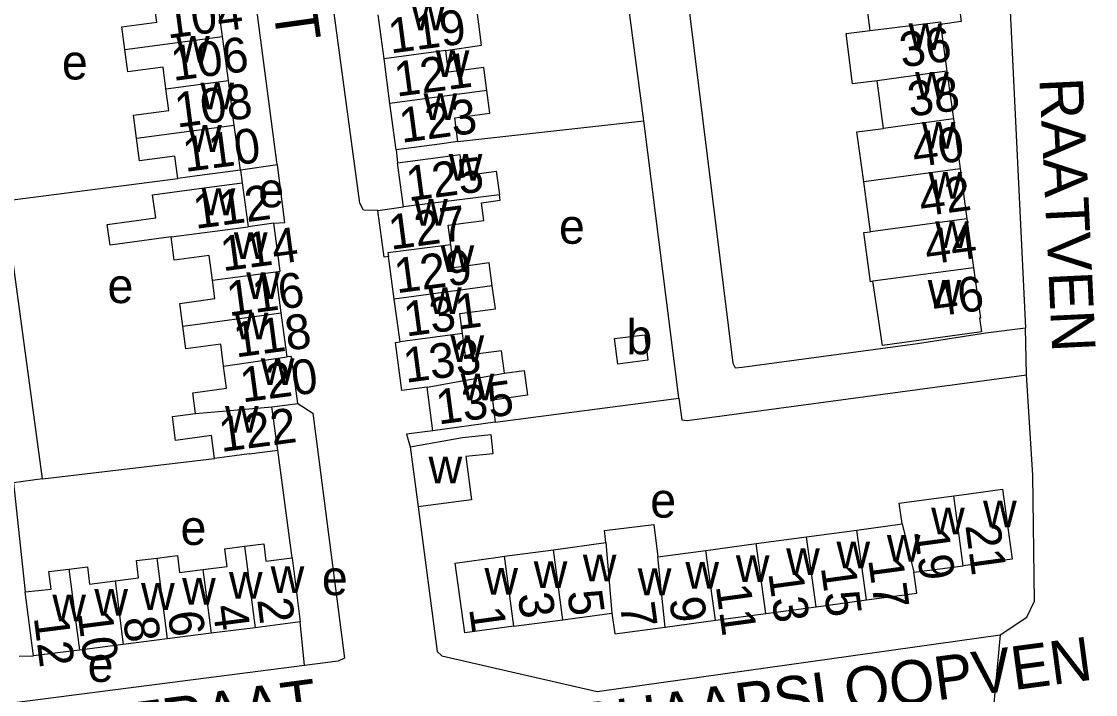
# Model space of a CAD drawing. Extents: x 162667 to 164645, y 379003 to 382150.
# Drawn here: x 163473.8 to 163597.3, y 381098.1 to 381175.5 of the extents above; entities that cross this region are included whole.
import ezdxf

# ---------------------------------------------------------------- set-up
doc = ezdxf.new("R2010")
doc.units = 0
for name, color, linetype in [('BLT_Basislijn', 7, 'Continuous'), ('BLT_Bebouwing', 7, 'Continuous'), ('BLT_Centroide', 7, 'Continuous'), ('BLT_Huisnummer', 7, 'Continuous'), ('BLT_Huisnummer_ tussenligend', 7, 'Continuous'), ('BLT_Onderverdeling_panden', 7, 'Continuous'), ('BLT_Straatnaam', 7, 'Continuous'), ('BLT_Vlakafsluiter', 7, 'Continuous')]:
    doc.layers.add(name, color=color, linetype=linetype)

msp = doc.modelspace()

# ---------------------------------------------------------------- linework, layer by layer
at = {"layer": 'BLT_Basislijn'}
for p, q in [((163545.35, 381164.05), (163541.22, 381195.04)), ((163586.86, 381189.28), (163589.19, 381140.23)), ((163523.97, 381161.65), (163545.35, 381164.05)), ((163516.88, 381160.7), (163517.04, 381159.2)), ((163503.22, 381158.97), (163498.97, 381158.38)), ((163498.97, 381158.38), (163499.18, 381156.92)), ((163471.9, 381154.85), (163491.77, 381157.41)), ((163476.23, 381122.88), (163471.97, 381154.32)), ((163589.34, 381134.85), (163589.19, 381140.23)), ((163528.27, 381129.39), (163549.38, 381132.18)), ((163504.92, 381113.81), (163503.26, 381126.2)), ((163476.23, 381122.88), (163496, 381125.22)), ((163506.35, 381101.46), (163505.85, 381106.45)), ((163473.56, 381102.51), (163475.18, 381102.55))]:
    msp.add_line(p, q, dxfattribs=at)
for points in [[(163546.24, 381211.73), (163555.57, 381136.18), (163555.85, 381135.67), (163556.64, 381135.74), (163576.78, 381138.45), (163584.66, 381139.68), (163589.19, 381140.23)], [(163514.78, 381153.75), (163513.12, 381153.77), (163512.72, 381154.57), (163507.84, 381190.6)], [(163503.22, 381158.97), (163503.18, 381159.27), (163499.22, 381189.4)], [(163549.38, 381132.18), (163549.33, 381132.5), (163545.35, 381164.05)], [(163502.83, 381152.26), (163504.07, 381152.35), (163503.22, 381158.97)], [(163549.38, 381132.18), (163549.72, 381129.68), (163550.31, 381129.61), (163589.34, 381134.85)], [(163586.31, 381104.98), (163589.37, 381107), (163590.24, 381108.83), (163590.03, 381123.33), (163589.34, 381134.85)], [(163505.58, 381131.57), (163507.29, 381130.46), (163510.93, 381102.28), (163510.22, 381101.93), (163506.35, 381101.46)], [(163521.1, 381128.43), (163518.08, 381128.03), (163518.48, 381126.56)], [(163476.23, 381122.88), (163472.91, 381122.44), (163474.24, 381109.92)], [(163519.41, 381119.67), (163521.6, 381103.05), (163522.14, 381102.57), (163539.99, 381098.46), (163586.31, 381104.98)], [(163506.35, 381101.46), (163450.08, 381094.2), (163448.63, 381104.37)]]:
    msp.add_lwpolyline(points, dxfattribs=at)
at = {"layer": 'BLT_Bebouwing'}
for p, q in [((163496.9, 381173.74), (163496.23, 381178.79)), ((163515.48, 381171.16), (163514.8, 381176.2)), ((163579.45, 381175.11), (163580.18, 381169.73)), ((163497.59, 381168.67), (163496.9, 381173.74)), ((163516.16, 381166.04), (163515.48, 381171.16)), ((163580.18, 381169.73), (163580.92, 381164.26)), ((163498.27, 381163.55), (163497.59, 381168.67)), ((163572.88, 381163.17), (163572.14, 381168.63)), ((163516.88, 381160.7), (163516.16, 381166.04)), ((163498.97, 381158.38), (163498.27, 381163.55)), ((163580.92, 381164.26), (163581.7, 381158.51)), ((163517.72, 381154.14), (163517.04, 381159.2)), ((163581.7, 381158.51), (163582.47, 381152.77)), ((163571.39, 381151.29), (163570.62, 381157.02)), ((163499.18, 381156.92), (163499.86, 381151.85)), ((163514.78, 381153.75), (163517.72, 381154.14)), ((163502.83, 381152.26), (163499.86, 381151.85)), ((163582.47, 381152.77), (163583.23, 381147.15)), ((163516.66, 381143.55), (163516.01, 381148.43)), ((163503.67, 381141.96), (163503.03, 381146.69)), ((163517.32, 381138.64), (163516.66, 381143.55)), ((163504.34, 381136.9), (163503.67, 381141.96)), ((163521.1, 381128.43), (163520.43, 381133.44)), ((163502.59, 381131.17), (163505.58, 381131.57)), ((163503.26, 381126.2), (163502.59, 381131.17)), ((163528.27, 381129.39), (163521.1, 381128.43)), ((163500, 381125.76), (163503.26, 381126.2)), ((163518.48, 381126.56), (163519.41, 381119.67)), ((163569.84, 381117.01), (163575.02, 381117.71)), ((163558.27, 381115.45), (163564.05, 381116.23)), ((163564.05, 381116.23), (163569.84, 381117.01)), ((163497.19, 381114.86), (163499.45, 381115.14)), ((163499.45, 381115.14), (163501.65, 381115.43)), ((163552.48, 381114.67), (163558.27, 381115.45)), ((163487.02, 381113.5), (163489.36, 381113.78)), ((163489.36, 381113.78), (163491.73, 381114.1)), ((163504.92, 381113.81), (163505.85, 381106.45)), ((163529.33, 381113.99), (163534.97, 381114.75)), ((163546.95, 381113.92), (163552.48, 381114.67)), ((163476.96, 381112.23), (163479.26, 381112.51)), ((163479.26, 381112.51), (163481.4, 381112.79)), ((163576.36, 381112.17), (163582.03, 381112.91)), ((163475.18, 381102.55), (163474.24, 381109.92)), ((163565.13, 381108.2), (163570.92, 381108.98)), ((163559.35, 381107.42), (163565.13, 381108.2)), ((163505.85, 381106.45), (163500.66, 381105.79)), ((163530.39, 381105.96), (163536.04, 381106.71)), ((163536.04, 381106.71), (163541.68, 381107.46)), ((163547.78, 381105.86), (163553.57, 381106.64)), ((163553.57, 381106.64), (163559.35, 381107.42)), ((163495.61, 381105.15), (163490.56, 381104.51)), ((163500.66, 381105.79), (163495.61, 381105.15)), ((163485.52, 381103.87), (163480.47, 381103.22)), ((163490.56, 381104.51), (163485.52, 381103.87)), ((163480.47, 381103.22), (163475.18, 381102.55))]:
    msp.add_line(p, q, dxfattribs=at)
for points in [[(163581.05, 381181.32), (163581.83, 381175.46), (163579.45, 381175.11)], [(163571.36, 381174.42), (163570.61, 381180.04), (163573.01, 381180.24)], [(163485.68, 381172.24), (163485.33, 381174.82), (163489.37, 381175.36), (163489.04, 381177.82)], [(163522.57, 381172.11), (163526.69, 381172.74), (163526.37, 381175.16), (163526.03, 381177.71)], [(163572.14, 381168.63), (163569.32, 381168.29), (163568.61, 381174.09), (163571.36, 381174.42)], [(163490.42, 381167.71), (163490.09, 381170.19), (163486.02, 381169.65), (163485.68, 381172.24)], [(163527.3, 381167.54), (163526.95, 381170.16), (163522.9, 381169.61), (163522.57, 381172.11)], [(163487.04, 381162.05), (163486.68, 381164.68), (163490.76, 381165.23), (163490.42, 381167.71)], [(163523.97, 381161.65), (163523.61, 381164.38), (163527.65, 381164.93), (163527.3, 381167.54)], [(163570.62, 381157.02), (163569.84, 381162.76), (163572.88, 381163.17)], [(163491.77, 381157.41), (163491.43, 381159.96), (163487.39, 381159.42), (163487.04, 381162.05)], [(163523.97, 381161.65), (163521.84, 381161.36), (163516.88, 381160.7)], [(163517.04, 381159.2), (163521.99, 381159.86), (163524.19, 381160.16), (163524.52, 381157.73), (163528.38, 381158.24), (163528.74, 381155.55)], [(163498.97, 381158.38), (163494.01, 381157.71), (163491.77, 381157.41)], [(163491, 381150.69), (163483.99, 381149.76), (163483.67, 381152.14), (163489.24, 381152.89), (163488.89, 381155.54), (163494.22, 381156.25), (163499.18, 381156.92)], [(163523.16, 381149.78), (163522.85, 381152.04), (163526.96, 381152.6), (163526.69, 381154.61), (163528.83, 381154.9), (163528.74, 381155.55)], [(163516.01, 381148.43), (163515.51, 381148.36), (163514.78, 381153.75)], [(163503.03, 381146.69), (163503.56, 381146.76), (163502.83, 381152.26)], [(163571.67, 381145.6), (163571.41, 381145.52), (163570.64, 381151.19), (163571.39, 381151.29)], [(163495.76, 381145.72), (163495.37, 381148.56), (163491.36, 381148.03), (163491, 381150.69)], [(163527.92, 381145.07), (163527.57, 381147.7), (163523.51, 381147.16), (163523.16, 381149.78)], [(163583.23, 381147.15), (163584.02, 381141.36), (163583.92, 381141.34), (163584.13, 381139.8), (163572.76, 381138.23), (163571.67, 381145.6)], [(163492.36, 381140.45), (163492.01, 381143.06), (163496.04, 381143.6), (163495.76, 381145.72)], [(163524.52, 381139.6), (163524.21, 381141.89), (163528.28, 381142.43), (163527.92, 381145.07)], [(163497.05, 381135.84), (163496.71, 381138.38), (163492.71, 381137.84), (163492.36, 381140.45)], [(163520.43, 381133.44), (163517.53, 381133.05), (163516.79, 381138.56), (163517.32, 381138.64)], [(163529.31, 381135.05), (163528.97, 381137.61), (163524.86, 381137.06), (163524.52, 381139.6)], [(163505.58, 381131.57), (163504.86, 381136.97), (163504.34, 381136.9)], [(163493.81, 381130.4), (163493.49, 381132.79), (163497.39, 381133.31), (163497.05, 381135.84)], [(163529.31, 381135.05), (163531.59, 381135.36), (163531.98, 381132.5), (163527.93, 381131.95), (163528.27, 381129.39)], [(163496, 381125.22), (163495.64, 381127.86), (163491.52, 381127.3), (163491.16, 381130.05), (163493.81, 381130.4)], [(163518.48, 381126.56), (163524.52, 381127.66), (163527.75, 381127.99), (163527.98, 381125.77), (163524.88, 381125.46), (163525.55, 381120.5), (163519.41, 381119.67)], [(163500, 381125.76), (163498.28, 381125.53), (163496, 381125.22)], [(163580.97, 381120.94), (163581.6, 381121.03), (163586.58, 381121.7), (163587.69, 381113.65), (163582.03, 381112.91)], [(163575.02, 381117.71), (163574.7, 381120.1), (163580.97, 381120.94)], [(163540.98, 381115.57), (163540.81, 381116.94), (163546.49, 381117.63), (163546.95, 381113.92)], [(163501.65, 381115.43), (163501.91, 381113.43), (163504.92, 381113.81)], [(163534.97, 381114.75), (163540.98, 381115.57)], [(163491.73, 381114.1), (163491.98, 381112.12), (163494.66, 381112.47)], [(163494.66, 381112.47), (163497.45, 381112.82), (163497.19, 381114.86)], [(163530.39, 381105.96), (163524.75, 381105.2), (163523.65, 381113.22), (163528.61, 381113.89), (163529.33, 381113.99)], [(163481.4, 381112.79), (163481.65, 381110.8), (163484.57, 381111.17)], [(163484.57, 381111.17), (163487.27, 381111.51), (163487.02, 381113.5)], [(163474.24, 381109.92), (163477.22, 381110.21), (163476.96, 381112.23)], [(163570.92, 381108.98), (163576.7, 381109.76), (163576.36, 381112.17)], [(163541.68, 381107.46), (163542, 381105.08), (163547.78, 381105.86)]]:
    msp.add_lwpolyline(points, dxfattribs=at)
msp.add_lwpolyline([(163541.98, 381139.02), (163545.45, 381139.45), (163545.82, 381136.52), (163542.34, 381136.09)], close=True, dxfattribs=at)
at = {"layer": 'BLT_Onderverdeling_panden'}
for p, q in [((163485.68, 381172.24), (163496.9, 381173.74)), ((163522.57, 381172.11), (163515.48, 381171.16)), ((163580.18, 381169.73), (163572.14, 381168.63)), ((163490.42, 381167.71), (163497.59, 381168.67)), ((163527.3, 381167.54), (163516.16, 381166.04)), ((163487.04, 381162.05), (163498.27, 381163.55)), ((163580.92, 381164.26), (163572.88, 381163.17)), ((163581.7, 381158.51), (163570.62, 381157.02)), ((163528.74, 381155.55), (163517.72, 381154.14)), ((163582.47, 381152.77), (163571.39, 381151.29)), ((163491, 381150.69), (163499.86, 381151.85)), ((163583.23, 381147.15), (163571.67, 381145.6)), ((163495.76, 381145.72), (163503.03, 381146.69)), ((163527.92, 381145.07), (163516.66, 381143.55)), ((163492.36, 381140.45), (163503.67, 381141.96)), ((163524.52, 381139.6), (163517.32, 381138.64)), ((163497.05, 381135.84), (163504.34, 381136.9)), ((163520.43, 381133.44), (163529.31, 381135.05)), ((163493.81, 381130.4), (163502.59, 381131.17)), ((163582.03, 381112.91), (163580.97, 381120.94)), ((163575.02, 381117.71), (163576.36, 381112.17)), ((163565.13, 381108.2), (163564.05, 381116.23)), ((163570.92, 381108.98), (163569.84, 381117.01)), ((163499.45, 381115.14), (163500.66, 381105.79)), ((163540.98, 381115.57), (163541.68, 381107.46)), ((163559.35, 381107.42), (163558.27, 381115.45)), ((163489.36, 381113.78), (163490.56, 381104.51)), ((163530.39, 381105.96), (163529.33, 381113.99)), ((163536.04, 381106.71), (163534.97, 381114.75)), ((163547.78, 381105.86), (163546.95, 381113.92)), ((163553.57, 381106.64), (163552.48, 381114.67)), ((163479.26, 381112.51), (163480.47, 381103.22)), ((163494.66, 381112.47), (163495.61, 381105.15)), ((163484.57, 381111.17), (163485.52, 381103.87))]:
    msp.add_line(p, q, dxfattribs=at)
for points in [[(163571.36, 381174.42), (163579.42, 381175.4), (163579.45, 381175.11)], [(163523.16, 381149.78), (163515.92, 381148.87), (163516.01, 381148.43)]]:
    msp.add_lwpolyline(points, dxfattribs=at)
at = {"layer": 'BLT_Vlakafsluiter'}
msp.add_line((163586.31, 381104.98), (163585.52, 381096.69), dxfattribs=at)

# ---------------------------------------------------------------- texts
at = {"layer": 'BLT_Centroide'}
for s, p in [('w', (163518.64, 381174.44)), ('w', (163575.77, 381172.16)), ('w', (163491.59, 381170.72)), ('e', (163478.46, 381168.79)), ('w', (163521.42, 381169.06)), ('w', (163576.52, 381166.59)), ('w', (163494.38, 381165.34)), ('w', (163520.03, 381164.12)), ('w', (163492.97, 381160.47)), ('w', (163577.29, 381160.84)), ('w', (163522.92, 381157.16)), ('e', (163501.03, 381154.1)), ('w', (163578.06, 381155.09)), ('w', (163494.52, 381153.19)), ('w', (163518.95, 381151.97)), ('e', (163535.59, 381149.91)), ('w', (163578.83, 381149.41)), ('w', (163498.23, 381148.14)), ('w', (163521.98, 381146.66)), ('e', (163483.7, 381143.09)), ('w', (163499.65, 381143.56)), ('w', (163520.55, 381141.84)), ('w', (163577.96, 381142.69)), ('w', (163498.32, 381138.91)), ('b', (163543.34, 381137.21)), ('w', (163523.12, 381136.31)), ('w', (163501.32, 381133.69)), ('w', (163524.29, 381131.91)), ('w', (163497.2, 381128.19)), ('w', (163520.6, 381122.36)), ('e', (163546.08, 381118.44)), ('w', (163584.33, 381117.31)), ('w', (163578.36, 381116.52)), ('e', (163492.09, 381115.3)), ('w', (163573.27, 381113.38)), ('w', (163567.48, 381112.61)), ('w', (163538.33, 381111.11)), ('w', (163555.92, 381111.05)), ('w', (163561.7, 381111.83)), ('w', (163502.45, 381109.77)), ('e', (163508.34, 381109.53)), ('w', (163527.02, 381109.59)), ('w', (163532.69, 381110.34)), ('w', (163544.64, 381109.52)), ('w', (163550.12, 381110.27)), ('w', (163492.28, 381108.44)), ('w', (163497.66, 381109.12)), ('w', (163482.19, 381107.16)), ('w', (163487.56, 381107.84)), ('w', (163477.36, 381106.53)), ('e', (163481.42, 381099.56))]:
    msp.add_text(s, height=4, dxfattribs=at).set_placement(p)
at = {"layer": 'BLT_Huisnummer'}
for s, rotation, p in [('104', 7.5401, (163490.6, 381173.48)), ('119', 7.602, (163516.23, 381171.77)), ('36', 7.7135, (163575, 381170.16)), ('108', 7.5401, (163491.69, 381163.25)), ('123', 7.602, (163517.5, 381161.5)), ('40', 7.7135, (163576.45, 381158.69)), ('112', 7.5401, (163493.81, 381151.61)), ('127', 7.602, (163516.26, 381149.21)), ('116', 7.5401, (163497.66, 381141.57)), ('46', 7.7135, (163578.72, 381141.52)), ('131', 7.602, (163518.02, 381139.24)), ('135', 7.602, (163521.73, 381129.13)), ('122', 7.5401, (163496.76, 381125.97)), ('21', 277.7824, (163582.28, 381117.55)), ('17', 277.7824, (163571.12, 381113.63)), ('13', 277.7824, (163559.64, 381112.07)), ('2', 277.2533, (163500.9, 381109.02)), ('5', 277.7824, (163536.53, 381109.91)), ('9', 277.7824, (163548.25, 381109.11)), ('6', 277.2447, (163490.62, 381107.53)), ('1', 277.7824, (163525.25, 381107.98)), ('12', 277.2437, (163475.22, 381106.98))]:
    msp.add_text(s, height=4, rotation=rotation, dxfattribs=at).set_placement(p)
at = {"layer": 'BLT_Huisnummer_ tussenligend'}
for s, rotation, p in [('106', 7.5401, (163491.25, 381168.61)), ('121', 7.602, (163516.92, 381166.8)), ('38', 7.7135, (163575.93, 381164.5)), ('110', 7.5401, (163492.62, 381158.15)), ('125', 7.602, (163518.29, 381154.79)), ('42', 7.7135, (163577.25, 381153.03)), ('44', 7.7135, (163577.89, 381147.5)), ('114', 7.5401, (163496.95, 381146.74)), ('129', 7.602, (163516.93, 381144.21)), ('118', 7.5401, (163498.46, 381136.84)), ('133', 7.602, (163517.97, 381133.92)), ('120', 7.5401, (163499.21, 381131.67)), ('19', 277.7824, (163576.38, 381116.92)), ('15', 277.7824, (163565.68, 381112.73)), ('11', 277.7824, (163553.6, 381110.59)), ('3', 277.7824, (163530.84, 381109.61)), ('4', 277.2533, (163495.77, 381108.25)), ('7', 277.7824, (163542.58, 381108.48)), ('10', 277.2447, (163480.26, 381107.49)), ('8', 277.2447, (163485.49, 381106.87))]:
    msp.add_text(s, height=4, rotation=rotation, dxfattribs=at).set_placement(p)
at = {"layer": 'BLT_Straatnaam'}
for s, rotation, p in [('LEEUWENSTRAAT', 277.9059, (163495.11, 381231.77)), ('RAATVEN', 272.7223, (163590.79, 381168.9)), ('SCHAAPSLOOPVEN', 7.6049, (163533.36, 381091.33)), ('TAPIRSTRAAT', 7.5541, (163462.37, 381088.93))]:
    msp.add_text(s, height=5, rotation=rotation, dxfattribs=at).set_placement(p)

doc.saveas('drawing.dxf')
